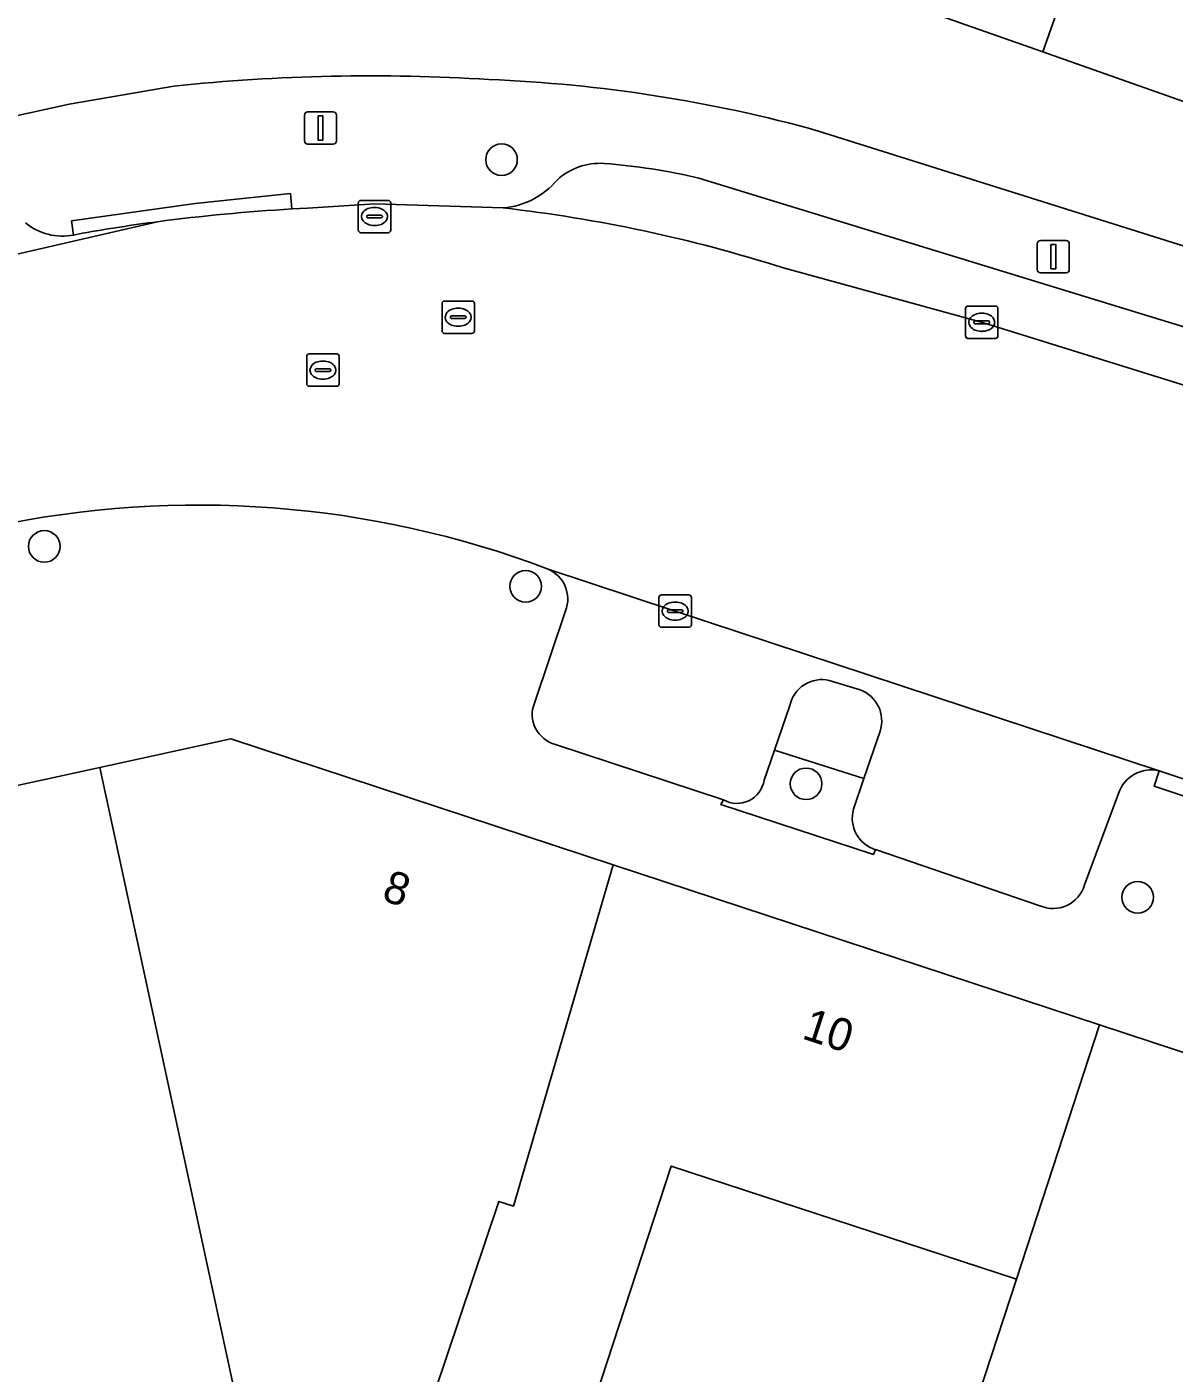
# Model space of a CAD drawing. Extents: x 160554 to 161248, y 385329 to 386506.
# Drawn here: x 160836.89 to 160872.36, y 385896.47 to 385938.11 of the extents above; entities that cross this region are included whole.
import ezdxf

# ---------------------------------------------------------------- set-up
doc = ezdxf.new("R2010")
doc.units = 0
for name, color, linetype in [('IMGEO_Boom', 7, 'Continuous'), ('IMGEO_Erf', 7, 'Continuous'), ('IMGEO_Groenvoorziening', 7, 'Continuous'), ('IMGEO_Kolk', 7, 'Continuous'), ('IMGEO_Lichtmast', 7, 'Continuous'), ('IMGEO_Pand', 7, 'Continuous'), ('IMGEO_Pand_nummerreeks', 7, 'Continuous'), ('IMGEO_Parkeervlak_open', 7, 'Continuous'), ('IMGEO_Rijbaan_lokaal_gesloten', 7, 'Continuous'), ('IMGEO_Rioolput', 7, 'Continuous'), ('IMGEO_Verkeerseiland_open', 7, 'Continuous'), ('IMGEO_Voetpad_open', 7, 'Continuous')]:
    doc.layers.add(name, color=color, linetype=linetype)

msp = doc.modelspace()

# ---------------------------------------------------------------- linework, layer by layer
at = {"layer": 'IMGEO_Boom'}
for centre in [(160851.565, 385934.003), (160837.424, 385922.041), (160852.311, 385920.806), (160860.985, 385914.7), (160871.235, 385911.19)]:
    msp.add_circle(centre, 0.489, dxfattribs=at)
at = {"layer": 'IMGEO_Erf'}
for points in [[(160861.372, 385934.889), (160883.981, 385927.769), (160885.54, 385932.667), (160880.779, 385934.348), (160880.335, 385933.09), (160874.235, 385935.243), (160868.3, 385937.337), (160862.365, 385939.432), (160856.43, 385941.526), (160850.495, 385943.621), (160844.396, 385945.773), (160846.06, 385950.488)], [(160791.225, 385925.374), (160838.197, 385935.721), (160841.431, 385936.281)]]:
    msp.add_lwpolyline(points, dxfattribs=at)
msp.add_lwpolyline([(160867.486, 385899.383), (160856.815, 385902.876), (160854.484, 385895.754), (160865.156, 385892.262)], close=True, dxfattribs=at)
for centre, radius, start, end in [((160847.499, 385878.423), 58.175, 86.37548, 95.98751), ((160849.474, 385892.163), 44.352, 74.4389, 87.7994)]:
    msp.add_arc(centre, radius, start, end, dxfattribs=at)
at = {"layer": 'IMGEO_Groenvoorziening'}
for points in [[(160862.45, 385913.917), (160862.772, 385914.863), (160860.005, 385915.743), (160859.684, 385914.813)], [(160858.428, 385914.205), (160858.347, 385914.06), (160863.065, 385912.514), (160863.133, 385912.664)]]:
    msp.add_lwpolyline(points, dxfattribs=at)
for centre, radius, start, end in [((160858.847, 385914.941), 0.847, 240.3744, 351.2867), ((160863.438, 385913.643), 1.026, 164.514, 252.6749)]:
    msp.add_arc(centre, radius, start, end, dxfattribs=at)
at = {"layer": 'IMGEO_Kolk'}
for p, q in [((160847.137, 385931.82), (160847.137, 385932.672)), ((160847.212, 385932.746), (160848.064, 385932.746)), ((160847.625, 385932.526), (160847.65, 385932.526)), ((160848.138, 385932.672), (160848.138, 385931.82)), ((160847.396, 385932.24), (160847.396, 385932.252)), ((160847.834, 385932.203), (160847.436, 385932.203)), ((160847.439, 385932.289), (160847.837, 385932.289)), ((160847.88, 385932.252), (160847.88, 385932.24)), ((160848.064, 385931.746), (160847.212, 385931.746)), ((160847.648, 385931.966), (160847.623, 385931.966)), ((160865.914, 385928.549), (160865.914, 385929.401)), ((160865.989, 385929.475), (160866.841, 385929.475)), ((160866.402, 385929.255), (160866.427, 385929.255)), ((160866.915, 385929.401), (160866.915, 385928.549)), ((160866.173, 385928.969), (160866.173, 385928.981)), ((160866.611, 385928.932), (160866.213, 385928.932)), ((160866.216, 385929.018), (160866.614, 385929.018)), ((160866.425, 385928.695), (160866.4, 385928.695)), ((160866.657, 385928.981), (160866.657, 385928.969)), ((160866.841, 385928.475), (160865.989, 385928.475)), ((160856.434, 385919.616), (160856.434, 385920.468)), ((160856.509, 385920.542), (160857.361, 385920.542)), ((160857.435, 385920.468), (160857.435, 385919.616)), ((160856.693, 385920.036), (160856.693, 385920.048)), ((160857.131, 385919.999), (160856.733, 385919.999)), ((160856.736, 385920.085), (160857.134, 385920.085)), ((160856.922, 385920.322), (160856.947, 385920.322)), ((160857.177, 385920.048), (160857.177, 385920.036)), ((160857.361, 385919.542), (160856.509, 385919.542)), ((160856.945, 385919.762), (160856.92, 385919.762))]:
    msp.add_line(p, q, dxfattribs=at)
for points in [[(160847.137, 385931.82), (160847.137, 385932.672)], [(160847.212, 385932.746), (160848.064, 385932.746)], [(160848.138, 385932.672), (160848.138, 385931.82)], [(160848.064, 385931.746), (160847.212, 385931.746)], [(160865.914, 385928.549), (160865.914, 385929.401)], [(160865.989, 385929.475), (160866.841, 385929.475)], [(160866.915, 385929.401), (160866.915, 385928.549)], [(160866.841, 385928.475), (160865.989, 385928.475)], [(160856.434, 385919.616), (160856.434, 385920.468)], [(160856.509, 385920.542), (160857.361, 385920.542)], [(160857.435, 385920.468), (160857.435, 385919.616)], [(160857.361, 385919.542), (160856.509, 385919.542)]]:
    msp.add_lwpolyline(points, dxfattribs=at)
for centre, radius, start, end in [((160847.214, 385932.67), 0.0765, 91.552, 178.448), ((160847.214, 385932.67), 0.0765, 91.552, 178.448), ((160848.062, 385932.67), 0.0765, 1.552, 88.448), ((160848.062, 385932.67), 0.0765, 1.552, 88.448), ((160847.436, 385932.249), 0.0403, 85.8775, 175.7526), ((160847.433, 385932.239), 0.0366, 178.938, 274.7102), ((160847.837, 385932.246), 0.043, 264.8664, 352.4533), ((160847.841, 385932.251), 0.0386, 1.7309, 96.639), ((160847.214, 385931.822), 0.0765, 181.552, 268.448), ((160847.214, 385931.822), 0.0765, 181.552, 268.448), ((160848.062, 385931.822), 0.0765, 271.552, 358.448), ((160848.062, 385931.822), 0.0765, 271.552, 358.448), ((160865.991, 385929.399), 0.0765, 91.552, 178.448), ((160865.991, 385929.399), 0.0765, 91.552, 178.448), ((160866.839, 385929.399), 0.0765, 1.552, 88.448), ((160866.839, 385929.399), 0.0765, 1.552, 88.448), ((160866.213, 385928.978), 0.0403, 85.8775, 175.7526), ((160866.21, 385928.968), 0.0366, 178.938, 274.7102), ((160866.614, 385928.975), 0.043, 264.8664, 352.4533), ((160866.618, 385928.98), 0.0386, 1.7309, 96.639), ((160865.991, 385928.551), 0.0765, 181.552, 268.448), ((160865.991, 385928.551), 0.0765, 181.552, 268.448), ((160866.839, 385928.551), 0.0765, 271.552, 358.448), ((160866.839, 385928.551), 0.0765, 271.552, 358.448), ((160856.511, 385920.466), 0.0765, 91.552, 178.448), ((160856.511, 385920.466), 0.0765, 91.552, 178.448), ((160857.359, 385920.466), 0.0765, 1.552, 88.448), ((160857.359, 385920.466), 0.0765, 1.552, 88.448), ((160856.733, 385920.045), 0.0403, 85.8775, 175.7526), ((160856.73, 385920.035), 0.0366, 178.938, 274.7102), ((160857.134, 385920.042), 0.043, 264.8664, 352.4533), ((160857.138, 385920.047), 0.0386, 1.7309, 96.639), ((160856.511, 385919.618), 0.0765, 181.552, 268.448), ((160856.511, 385919.618), 0.0765, 181.552, 268.448), ((160857.359, 385919.618), 0.0765, 271.552, 358.448), ((160857.359, 385919.618), 0.0765, 271.552, 358.448)]:
    msp.add_arc(centre, radius, start, end, dxfattribs=at)
for centre, major_axis, ratio, start_param, end_param in [((160847.624, 385932.246), (-0.387, 0.002), 0.722429, 4.712389, 7.853982), ((160847.649, 385932.246), (-0.39, 0.002), 0.717154, 1.570796, 4.712389), ((160866.401, 385928.975), (-0.387, 0.002), 0.722429, 4.712389, 7.853982), ((160866.426, 385928.975), (-0.39, 0.002), 0.717154, 1.570796, 4.712389), ((160856.921, 385920.042), (-0.387, 0.002), 0.722429, 4.712389, 7.853982), ((160856.946, 385920.042), (-0.39, 0.002), 0.717154, 1.570796, 4.712389)]:
    msp.add_ellipse(centre, major_axis=major_axis, ratio=ratio, start_param=start_param, end_param=end_param, dxfattribs=at)
at = {"layer": 'IMGEO_Lichtmast'}
for p, q in [((160845.47, 385934.584), (160845.47, 385935.384)), ((160845.47, 385935.384), (160845.47, 385934.584)), ((160845.57, 385935.484), (160846.36, 385935.484)), ((160846.36, 385935.484), (160845.57, 385935.484)), ((160846.46, 385935.384), (160846.46, 385934.584)), ((160846.46, 385934.584), (160846.46, 385935.384)), ((160846.36, 385934.484), (160845.57, 385934.484)), ((160845.57, 385934.484), (160846.36, 385934.484)), ((160868.134, 385930.606), (160868.134, 385931.406)), ((160868.134, 385931.406), (160868.134, 385930.606)), ((160868.234, 385931.506), (160869.024, 385931.506)), ((160869.024, 385931.506), (160868.234, 385931.506)), ((160869.124, 385931.406), (160869.124, 385930.606)), ((160869.124, 385930.606), (160869.124, 385931.406)), ((160869.024, 385930.506), (160868.234, 385930.506)), ((160868.234, 385930.506), (160869.024, 385930.506))]:
    msp.add_line(p, q, dxfattribs=at)
for points in [[(160845.89, 385935.359), (160846.04, 385935.359), (160846.04, 385934.609), (160845.89, 385934.609), (160845.89, 385935.359)], [(160868.554, 385931.381), (160868.704, 385931.381), (160868.704, 385930.631), (160868.554, 385930.631), (160868.554, 385931.381)]]:
    msp.add_lwpolyline(points, dxfattribs=at)
for centre, start, end in [((160845.57, 385935.384), 90, 180), ((160845.57, 385935.384), 90, 180), ((160846.36, 385935.384), 0, 90), ((160846.36, 385935.384), 360, 90), ((160845.57, 385934.584), 180, 270), ((160845.57, 385934.584), 180, 270), ((160846.36, 385934.584), 270, 0), ((160846.36, 385934.584), 270, 0), ((160868.234, 385931.406), 90, 180), ((160868.234, 385931.406), 90, 180), ((160869.024, 385931.406), 0, 90), ((160869.024, 385931.406), 360, 90), ((160868.234, 385930.606), 180, 270), ((160868.234, 385930.606), 180, 270), ((160869.024, 385930.606), 270, 0), ((160869.024, 385930.606), 270, 0)]:
    msp.add_arc(centre, 0.1, start, end, dxfattribs=at)
at = {"layer": 'IMGEO_Pand'}
for points in [[(160871.187, 385945.521), (160865.253, 385947.615), (160862.365, 385939.432), (160868.3, 385937.337)], [(160877.122, 385943.426), (160871.187, 385945.521), (160868.3, 385937.337), (160874.235, 385935.243)], [(160851.486, 385901.786), (160851.934, 385901.64), (160855.021, 385912.197), (160843.195, 385916.09), (160839.147, 385915.209), (160844.062, 385892.433), (160848.675, 385893.441)], [(160839.147, 385915.209), (160824.466, 385912.014), (160832.965, 385872.859), (160847.594, 385876.059), (160846.525, 385880.944), (160844.062, 385892.433)], [(160870.059, 385907.246), (160855.021, 385912.197), (160851.934, 385901.64), (160851.486, 385901.786), (160848.675, 385893.441), (160848.808, 385892.831), (160863.802, 385888.125), (160865.156, 385892.262), (160854.484, 385895.754), (160856.815, 385902.876), (160867.486, 385899.383)], [(160883.339, 385889.663), (160886.624, 385888.585), (160886.518, 385888.262), (160886.899, 385888.137), (160893.721, 385899.359), (160893.43, 385899.454), (160893.159, 385899.065), (160891.349, 385899.659), (160891.506, 385900.139), (160890.636, 385900.424), (160890.467, 385899.91), (160887.221, 385900.976), (160887.405, 385901.535), (160870.059, 385907.246), (160867.486, 385899.383), (160865.156, 385892.262), (160863.802, 385888.125), (160860.8, 385878.948), (160873.636, 385874.736), (160878.094, 385873.273), (160880.553, 385880.958)]]:
    msp.add_lwpolyline(points, close=True, dxfattribs=at)
at = {"layer": 'IMGEO_Parkeervlak_open'}
for points in [[(160877.339, 385927.4), (160857.671, 385933.434)], [(160745.49, 385911.828), (160750.518, 385912.437), (160756.492, 385913.428), (160759.912, 385914.039), (160763.809, 385914.925), (160787.915, 385920.21), (160816.018, 385926.352), (160840.924, 385932.085)], [(160838.608, 385931.728), (160838.334, 385931.674)], [(160860.248, 385930.666), (160866.444, 385928.966), (160880.216, 385924.684)], [(160871.904, 385915.104), (160856.936, 385920.042), (160852.978, 385921.354)], [(160853.546, 385920.046), (160852.581, 385917.199)], [(160861.701, 385917.9), (160862.651, 385917.608)], [(160859.684, 385914.813), (160860.005, 385915.743), (160860.481, 385917.123)], [(160863.27, 385916.327), (160862.772, 385914.863), (160862.45, 385913.917)], [(160853.231, 385915.921), (160858.428, 385914.205)], [(160869.596, 385911.575), (160870.643, 385914.405)], [(160863.133, 385912.664), (160868.21, 385910.93)]]:
    msp.add_lwpolyline(points, dxfattribs=at)
for centre, radius, start, end in [((160854.621, 385931.902), 1.991, 86.7121, 132.2957), ((160853.273, 385914.794), 19.152, 76.7228, 85.6206), ((160851.42, 385934.925), 2.422, 274.6134, 320.2098), ((160846.543, 385887.659), 45.138, 72.3246, 83.5484), ((160837.99, 385933.454), 1.813, 230.7524, 280.9402), ((160846.91, 385885.56), 46.908, 97.3316, 100.1942), ((160852.598, 385920.411), 1.016, 338.9275, 68.0184), ((160861.476, 385916.908), 1.018, 77.2057, 167.7792), ((160862.303, 385916.65), 1.02, 341.5488, 70.0324), ((160853.474, 385916.849), 0.959, 158.583, 255.3335), ((160871.659, 385914.059), 1.073, 76.7993, 161.2018), ((160858.847, 385914.941), 0.847, 240.3744, 351.2867), ((160863.438, 385913.643), 1.026, 164.514, 252.6749), ((160868.621, 385911.859), 1.016, 246.1552, 343.7563)]:
    msp.add_arc(centre, radius, start, end, dxfattribs=at)
at = {"layer": 'IMGEO_Rijbaan_lokaal_gesloten'}
for points in [[(160851.615, 385932.511), (160847.643, 385932.641), (160845.565, 385932.507), (160845.324, 385932.494), (160845.083, 385932.48)], [(160840.924, 385932.085), (160816.018, 385926.352), (160787.915, 385920.21), (160763.809, 385914.925), (160759.912, 385914.039), (160756.492, 385913.428), (160750.518, 385912.437), (160745.49, 385911.828), (160744.233, 385911.636), (160746.075, 385901.918), (160748.25, 385902.591)], [(160898.148, 385914.114), (160900.799, 385913.232), (160902.196, 385917.781), (160900.98, 385918.15), (160897.048, 385919.373), (160887.881, 385922.3), (160886.758, 385922.649), (160882.61, 385923.939), (160880.216, 385924.684), (160866.444, 385928.966), (160860.248, 385930.666)], [(160852.978, 385921.354), (160856.936, 385920.042), (160871.904, 385915.104), (160877.365, 385913.283), (160894.434, 385907.633), (160895.721, 385907.213), (160897.729, 385912.87)]]:
    msp.add_lwpolyline(points, dxfattribs=at)
for centre, radius, start, end in [((160848.627, 385873.069), 59.517, 93.41407, 97.43669), ((160846.543, 385887.659), 45.138, 72.3246, 83.5484), ((160842.189, 385892.775), 30.548, 69.3173, 101.9932)]:
    msp.add_arc(centre, radius, start, end, dxfattribs=at)
at = {"layer": 'IMGEO_Rioolput'}
for p, q in [((160849.725, 385928.706), (160849.725, 385929.558)), ((160849.8, 385929.632), (160850.652, 385929.632)), ((160850.726, 385929.558), (160850.726, 385928.706)), ((160849.984, 385929.126), (160849.984, 385929.138)), ((160850.027, 385929.175), (160850.425, 385929.175)), ((160850.213, 385929.412), (160850.238, 385929.412)), ((160850.468, 385929.138), (160850.468, 385929.126)), ((160850.422, 385929.089), (160850.024, 385929.089)), ((160850.236, 385928.852), (160850.211, 385928.852)), ((160850.652, 385928.632), (160849.8, 385928.632)), ((160845.542, 385927.07), (160845.542, 385927.922)), ((160845.617, 385927.996), (160846.469, 385927.996)), ((160846.543, 385927.922), (160846.543, 385927.07)), ((160845.801, 385927.49), (160845.801, 385927.502)), ((160846.239, 385927.453), (160845.841, 385927.453)), ((160845.844, 385927.539), (160846.242, 385927.539)), ((160846.03, 385927.776), (160846.055, 385927.776)), ((160846.285, 385927.502), (160846.285, 385927.49)), ((160846.053, 385927.216), (160846.028, 385927.216)), ((160846.469, 385926.996), (160845.617, 385926.996))]:
    msp.add_line(p, q, dxfattribs=at)
for points in [[(160849.725, 385928.706), (160849.725, 385929.558)], [(160849.8, 385929.632), (160850.652, 385929.632)], [(160850.726, 385929.558), (160850.726, 385928.706)], [(160850.652, 385928.632), (160849.8, 385928.632)], [(160845.542, 385927.07), (160845.542, 385927.922)], [(160845.617, 385927.996), (160846.469, 385927.996)], [(160846.543, 385927.922), (160846.543, 385927.07)], [(160846.469, 385926.996), (160845.617, 385926.996)]]:
    msp.add_lwpolyline(points, dxfattribs=at)
for centre, radius, start, end in [((160849.802, 385929.556), 0.0765, 91.552, 178.448), ((160849.802, 385929.556), 0.0765, 91.552, 178.448), ((160850.65, 385929.556), 0.0765, 1.552, 88.448), ((160850.65, 385929.556), 0.0765, 1.552, 88.448), ((160850.024, 385929.135), 0.0403, 85.8775, 175.7526), ((160850.021, 385929.125), 0.0366, 178.938, 274.7102), ((160850.425, 385929.132), 0.043, 264.8664, 352.4533), ((160850.429, 385929.137), 0.0386, 1.7309, 96.639), ((160849.802, 385928.708), 0.0765, 181.552, 268.448), ((160849.802, 385928.708), 0.0765, 181.552, 268.448), ((160850.65, 385928.708), 0.0765, 271.552, 358.448), ((160850.65, 385928.708), 0.0765, 271.552, 358.448), ((160845.619, 385927.92), 0.0765, 91.552, 178.448), ((160845.619, 385927.92), 0.0765, 91.552, 178.448), ((160846.467, 385927.92), 0.0765, 1.552, 88.448), ((160846.467, 385927.92), 0.0765, 1.552, 88.448), ((160845.841, 385927.499), 0.0403, 85.8775, 175.7526), ((160845.838, 385927.489), 0.0366, 178.938, 274.7102), ((160846.242, 385927.496), 0.043, 264.8664, 352.4533), ((160846.246, 385927.501), 0.0386, 1.7309, 96.639), ((160845.619, 385927.072), 0.0765, 181.552, 268.448), ((160845.619, 385927.072), 0.0765, 181.552, 268.448), ((160846.467, 385927.072), 0.0765, 271.552, 358.448), ((160846.467, 385927.072), 0.0765, 271.552, 358.448)]:
    msp.add_arc(centre, radius, start, end, dxfattribs=at)
for centre, major_axis, ratio, start_param, end_param in [((160850.212, 385929.132), (-0.387, 0.002), 0.722429, 4.712389, 7.853982), ((160850.237, 385929.132), (-0.39, 0.002), 0.717154, 1.570796, 4.712389), ((160846.029, 385927.496), (-0.387, 0.002), 0.722429, 4.712389, 7.853982), ((160846.054, 385927.496), (-0.39, 0.002), 0.717154, 1.570796, 4.712389)]:
    msp.add_ellipse(centre, major_axis=major_axis, ratio=ratio, start_param=start_param, end_param=end_param, dxfattribs=at)
at = {"layer": 'IMGEO_Verkeerseiland_open'}
for points in [[(160862.651, 385917.608), (160861.701, 385917.9)], [(160860.481, 385917.123), (160860.005, 385915.743), (160862.772, 385914.863), (160863.27, 385916.327)]]:
    msp.add_lwpolyline(points, dxfattribs=at)
for centre, radius, start, end in [((160861.476, 385916.908), 1.018, 77.2057, 167.7792), ((160862.303, 385916.65), 1.02, 341.5488, 70.0324)]:
    msp.add_arc(centre, radius, start, end, dxfattribs=at)
at = {"layer": 'IMGEO_Voetpad_open'}
for points in [[(160841.431, 385936.281), (160838.197, 385935.721), (160791.225, 385925.374), (160789.869, 385925.075), (160739.836, 385914.053)], [(160880.216, 385924.684), (160882.61, 385923.939), (160886.758, 385922.649), (160887.881, 385922.3), (160897.048, 385919.373), (160900.98, 385918.15), (160902.196, 385917.781), (160903.014, 385920.416), (160887.33, 385925.297), (160883.599, 385926.57), (160883.981, 385927.769), (160861.372, 385934.889)], [(160857.671, 385933.434), (160877.339, 385927.4)], [(160845.083, 385932.48), (160845.038, 385932.957), (160842.087, 385932.647), (160838.272, 385932.109), (160838.334, 385931.674), (160838.608, 385931.728)], [(160838.334, 385931.674), (160838.272, 385932.109), (160842.087, 385932.647), (160845.038, 385932.957), (160845.083, 385932.48), (160845.324, 385932.494), (160845.565, 385932.507), (160847.643, 385932.641), (160851.615, 385932.511)], [(160852.581, 385917.199), (160853.546, 385920.046)], [(160824.466, 385912.014), (160839.147, 385915.209), (160843.195, 385916.09), (160855.021, 385912.197), (160870.059, 385907.246), (160887.405, 385901.535), (160887.221, 385900.976), (160890.467, 385899.91), (160890.636, 385900.424), (160891.506, 385900.139), (160891.349, 385899.659), (160893.159, 385899.065), (160893.43, 385899.454), (160893.721, 385899.359), (160897.896, 385906.019)], [(160868.21, 385910.93), (160863.133, 385912.664), (160863.065, 385912.514), (160858.347, 385914.06), (160858.428, 385914.205), (160853.231, 385915.921)], [(160877.365, 385913.283), (160877.207, 385912.809), (160871.746, 385914.63), (160871.904, 385915.104)], [(160870.643, 385914.405), (160869.596, 385911.575)]]:
    msp.add_lwpolyline(points, dxfattribs=at)
msp.add_lwpolyline([(160871.904, 385915.104), (160871.746, 385914.63), (160877.207, 385912.809), (160877.365, 385913.283)], close=True, dxfattribs=at)
for centre, radius, start, end in [((160847.499, 385878.423), 58.175, 86.37548, 95.98751), ((160849.474, 385892.163), 44.352, 74.4389, 87.7994), ((160854.621, 385931.902), 1.991, 86.7121, 132.2957), ((160853.273, 385914.794), 19.152, 76.7228, 85.6206), ((160851.42, 385934.925), 2.422, 274.6134, 320.2098), ((160848.627, 385873.069), 59.517, 93.41407, 97.43669), ((160837.99, 385933.454), 1.813, 230.7524, 280.9402), ((160846.91, 385885.56), 46.908, 97.3316, 100.1942), ((160842.189, 385892.775), 30.548, 69.3173, 101.9932), ((160852.598, 385920.411), 1.016, 338.9275, 68.0184), ((160853.474, 385916.849), 0.959, 158.583, 255.3335), ((160871.659, 385914.059), 1.073, 76.7993, 161.2018), ((160868.621, 385911.859), 1.016, 246.1552, 343.7563)]:
    msp.add_arc(centre, radius, start, end, dxfattribs=at)

# ---------------------------------------------------------------- texts
at = {"layer": 'IMGEO_Pand_nummerreeks'}
for s, rotation, p in [('8', 341.7772, (160847.825, 385911.113)), ('10', 341.7799, (160860.819, 385906.835))]:
    msp.add_text(s, height=1, rotation=rotation, dxfattribs=at).set_placement(p)

doc.saveas('drawing.dxf')
